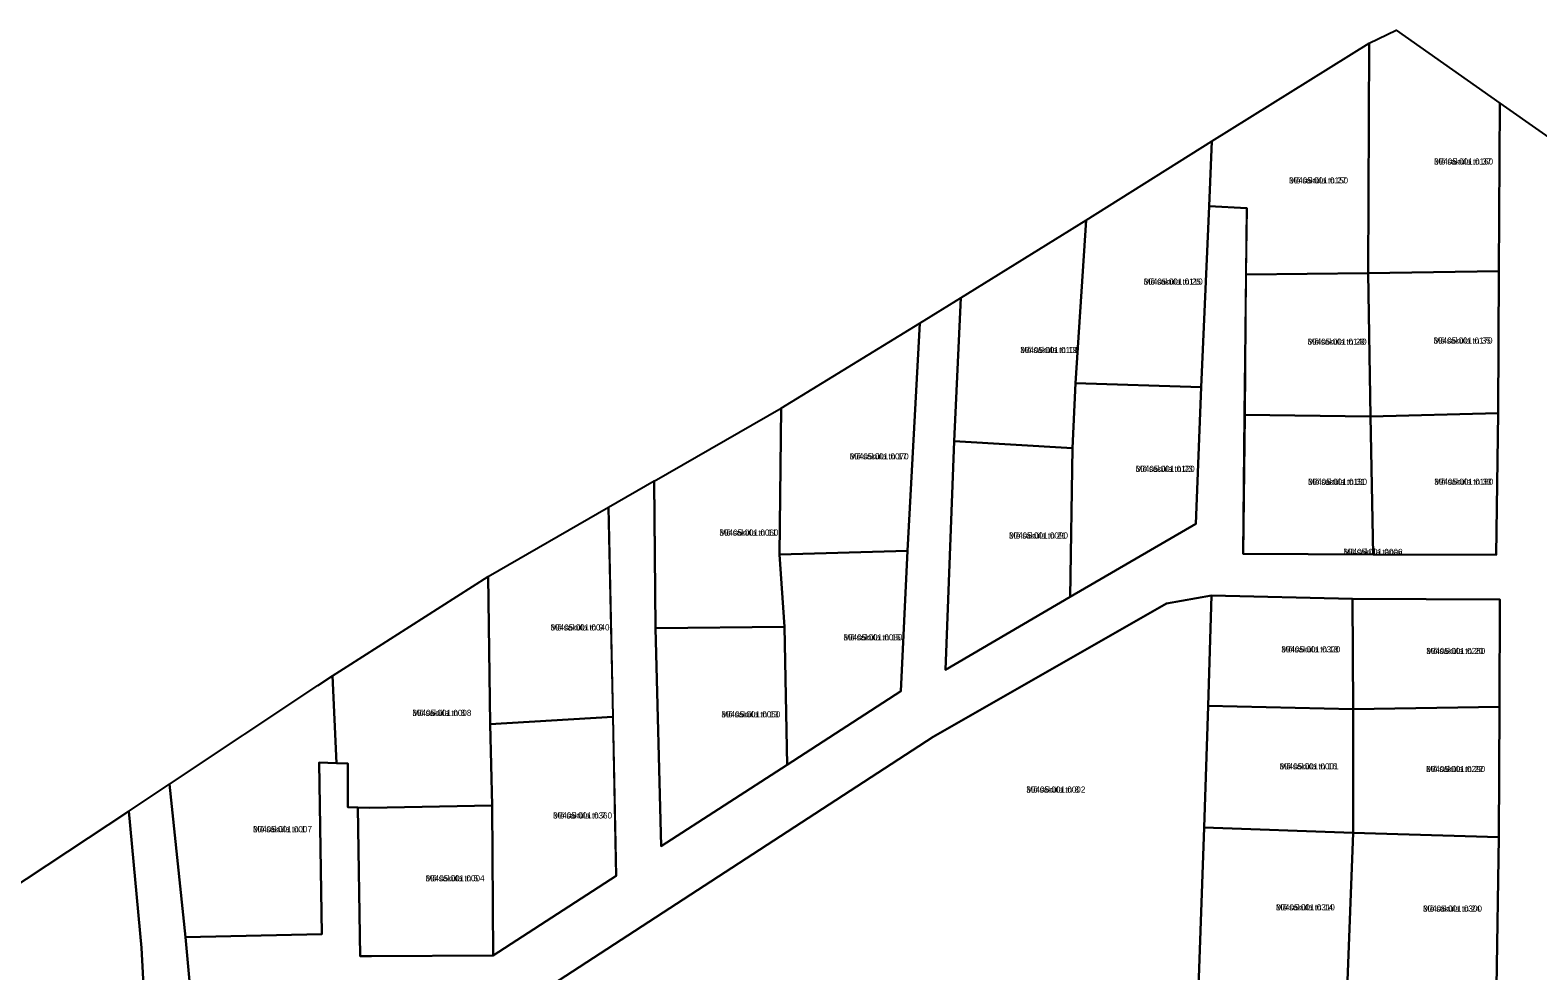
# Model space of a CAD drawing. Extents: x 542681 to 554572, y 6566489 to 6580482.
# Drawn here: x 547346 to 547716.5, y 6577162.8 to 6577394.2 of the extents above; entities that cross this region are included whole.
import ezdxf

# ---------------------------------------------------------------- set-up
doc = ezdxf.new("R2010")
doc.units = 0
for name, color, linetype in [('L_AADRESS', 7, 'Continuous'), ('PIIR', 7, 'Continuous'), ('TUNNUS', 7, 'Continuous')]:
    doc.layers.add(name, color=color, linetype=linetype)

msp = doc.modelspace()

# ---------------------------------------------------------------- linework, layer by layer
at = {"layer": 'PIIR'}
for points in [[(547644.82, 6577334.1), (547644.97, 6577350.38), (547635.72, 6577350.9), (547636.39, 6577366.9), (547675.03, 6577390.99), (547674.84, 6577334.44)], [(547675.03, 6577390.99), (547681.67, 6577394.18), (547707.19, 6577376.23), (547706.93, 6577334.87), (547674.84, 6577334.44)], [(547605.52, 6577347.47), (547636.39, 6577366.9), (547635.72, 6577350.9), (547633.79, 6577306.42), (547602.91, 6577307.35)], [(547574.67, 6577328.33), (547605.52, 6577347.47), (547602.91, 6577307.35), (547602.17, 6577291.41), (547573.06, 6577293.09)], [(547644.82, 6577334.1), (547674.84, 6577334.44), (547675.39, 6577299.16), (547644.46, 6577299.58)], [(547674.84, 6577334.44), (547706.93, 6577334.87), (547706.75, 6577299.95), (547675.39, 6577299.16)], [(547530.53, 6577301.2), (547564.65, 6577322.1), (547561.61, 6577266.15), (547530.1, 6577265.24)], [(547633.79, 6577306.42), (547632.45, 6577272.8), (547601.58, 6577254.82), (547602.17, 6577291.41), (547602.91, 6577307.35)], [(547499.35, 6577283.27), (547530.53, 6577301.2), (547530.1, 6577265.24), (547531.4, 6577247.45), (547499.7, 6577247.1)], [(547644.46, 6577299.58), (547675.39, 6577299.16), (547676.01, 6577265.26), (547644.06, 6577265.43)], [(547675.39, 6577299.16), (547706.75, 6577299.95), (547706.26, 6577265.14), (547676.01, 6577265.26)], [(547573.06, 6577293.09), (547602.17, 6577291.41), (547601.58, 6577254.82), (547570.9, 6577236.84)], [(547489.18, 6577225.35), (547459.02, 6577223.54), (547458.55, 6577259.85), (547488.12, 6577276.89)], [(547559.93, 6577231.66), (547532, 6577213.52), (547531.4, 6577247.45), (547530.1, 6577265.24), (547561.61, 6577266.15)], [(547420.28, 6577235.38), (547423.89, 6577237.69), (547458.55, 6577259.85), (547459.02, 6577223.54), (547459.55, 6577203.48), (547429.34, 6577202.96), (547426.5, 6577203.05), (547424.04, 6577203.11), (547424.05, 6577213.85), (547421.24, 6577213.95)], [(547472.42, 6577158.24), (547567.94, 6577220.42), (547625.27, 6577253.21), (547636.34, 6577255.13), (547635.46, 6577228.02), (547634.51, 6577198.07), (547633.12, 6577158.82), (547605.31, 6577158.73), (547569.42, 6577158.61), (547533.68, 6577158.5), (547497.57, 6577158.43)], [(547636.34, 6577255.13), (547670.95, 6577254.35), (547671.11, 6577227.17), (547635.46, 6577228.02)], [(547670.95, 6577254.35), (547707.18, 6577254.17), (547707.11, 6577227.76), (547671.11, 6577227.17)], [(547532, 6577213.52), (547501.05, 6577193.5), (547499.7, 6577247.1), (547531.4, 6577247.45)], [(547380.22, 6577208.72), (547416.67, 6577232.98), (547420.28, 6577235.38), (547421.24, 6577213.95), (547416.99, 6577214.06), (547417.69, 6577171.85), (547384.17, 6577171.13)], [(547635.46, 6577228.02), (547671.11, 6577227.17), (547671.14, 6577196.78), (547634.51, 6577198.07)], [(547671.11, 6577227.17), (547707.11, 6577227.76), (547706.91, 6577195.71), (547671.14, 6577196.78)], [(547459.55, 6577203.48), (547459.02, 6577223.54), (547489.18, 6577225.35), (547489.96, 6577186.18), (547459.79, 6577166.63)], [(547426.5, 6577203.05), (547429.34, 6577202.96), (547459.55, 6577203.48), (547459.79, 6577166.63), (547429.88, 6577166.46), (547427.11, 6577166.46)], [(547634.51, 6577198.07), (547671.14, 6577196.78), (547669.68, 6577158.28), (547641.57, 6577157.83), (547633.12, 6577158.82)], [(547669.68, 6577158.28), (547671.14, 6577196.78), (547706.91, 6577195.71), (547706.39, 6577158.87), (547677.53, 6577158.35)]]:
    msp.add_lwpolyline(points, close=True, dxfattribs=at)
for points in [[(547385.71, 6577154.03), (547384.17, 6577171.13), (547417.69, 6577171.85), (547416.99, 6577214.06), (547421.24, 6577213.95), (547424.05, 6577213.85), (547424.04, 6577203.11), (547426.5, 6577203.05), (547427.11, 6577166.46), (547429.88, 6577166.46), (547459.79, 6577166.63), (547489.96, 6577186.18), (547489.29, 6577225.38), (547488.12, 6577276.89), (547499.35, 6577283.32), (547499.7, 6577247.1), (547501.05, 6577193.5), (547532, 6577213.52), (547559.93, 6577231.66), (547561.61, 6577266.15), (547564.65, 6577322.1), (547574.67, 6577328.33), (547573.06, 6577293.09), (547570.9, 6577236.84), (547601.58, 6577254.82), (547632.45, 6577272.8), (547633.79, 6577306.42), (547635.72, 6577350.9), (547644.97, 6577350.38), (547644.77, 6577334.22), (547644.49, 6577299.52), (547644.06, 6577265.43), (547676.01, 6577265.26), (547706.26, 6577265.14), (547706.75, 6577299.95), (547706.93, 6577334.87), (547707.19, 6577376.23), (547737.58, 6577354.9)], [(547706.39, 6577158.87), (547706.91, 6577195.71), (547707.11, 6577227.76), (547707.18, 6577254.17), (547670.95, 6577254.35), (547636.34, 6577255.13), (547625.27, 6577253.21), (547567.94, 6577220.42), (547472.42, 6577158.24)], [(547365.05, 6576678.82), (547366.14, 6576847.48), (547372.9, 6576962.73), (547379.3, 6577030.03), (547379.42, 6577054.81), (547373.29, 6577168.48), (547370.25, 6577202.13), (547380.22, 6577208.72), (547384.14, 6577171.11), (547385.71, 6577154.03), (547386.78, 6577116.38), (547387.83, 6577116.57), (547392.31, 6577055.06), (547391.86, 6577051.02), (547390.49, 6577037.28), (547390.15, 6577032.14), (547388.95, 6577019.68), (547387.52, 6576999.24), (547384.13, 6576962.45), (547381.71, 6576921), (547378.68, 6576869.2), (547380.13, 6576867.09), (547380.13, 6576847.05), (547379.04, 6576678.28)], [(547274.87, 6577139.04), (547370.25, 6577202.13), (547373.29, 6577168.48), (547379.42, 6577054.81), (547379.3, 6577030.03), (547372.9, 6576962.73), (547366.14, 6576847.48), (547365.05, 6576678.82), (547361.87, 6576553.76), (547357.84, 6576545.81), (547342.59, 6576529.51)]]:
    msp.add_lwpolyline(points, dxfattribs=at)

# ---------------------------------------------------------------- texts
at = {"layer": 'L_AADRESS'}
for s, p in [('Mõisaküla tn 37', (547691.02, 6577361.13)), ('Mõisaküla tn 27', (547655.38, 6577356.48)), ('Mõisaküla tn 25', (547619.65, 6577331.6)), ('Mõisaküla tn 29', (547659.93, 6577316.82)), ('Mõisaküla tn 35', (547690.89, 6577317.1)), ('Mõisaküla tn 19', (547589.29, 6577314.78)), ('Mõisaküla tn 17', (547547.38, 6577288.63)), ('Mõisaküla tn 23', (547617.68, 6577285.55)), ('Mõisaküla tn 31', (547660.04, 6577282.36)), ('Mõisaküla tn 33', (547691.07, 6577282.38)), ('Mõisaküla tn 11', (547515.38, 6577269.88)), ('Mõisaküla tn 21', (547586.54, 6577269.16)), ('Mõisaküla tänav', (547668.75, 6577265.13)), ('Mõisaküla tn 9', (547473.86, 6577246.55)), ('Mõisaküla tn 15', (547545.86, 6577244.11)), ('Mõisaküla tn 18', (547653.46, 6577241.15)), ('Mõisaküla tn 20', (547689.09, 6577240.76)), ('Mõisaküla tn 3', (547439.91, 6577225.54)), ('Mõisaküla tn 13', (547515.85, 6577225.18)), ('Mõisaküla tn 16', (547653.04, 6577212.4)), ('Mõisaküla tn 22', (547689.07, 6577211.74)), ('Mõisaküla tn 8', (547590.81, 6577206.68)), ('Mõisaküla tn 7', (547474.49, 6577200.31)), ('Mõisaküla tn 1', (547400.73, 6577196.93)), ('Mõisaküla tn 5', (547443.14, 6577184.87)), ('Mõisaküla tn 14', (547652.13, 6577177.72)), ('Mõisaküla tn 24', (547688.29, 6577177.41))]:
    msp.add_text(s, height=1.5, dxfattribs=at).set_placement(p)
at = {"layer": 'TUNNUS'}
for s, p in [('30405:001:0160', (547691.02, 6577361.13)), ('30405:001:0150', (547655.38, 6577356.48)), ('30405:001:0110', (547619.65, 6577331.6)), ('30405:001:0140', (547659.93, 6577316.82)), ('30405:001:0170', (547690.89, 6577317.1)), ('30405:001:0100', (547589.29, 6577314.78)), ('30405:001:0070', (547547.38, 6577288.63)), ('30405:001:0120', (547617.68, 6577285.55)), ('30405:001:0130', (547660.04, 6577282.36)), ('30405:001:0180', (547691.07, 6577282.38)), ('30405:001:0060', (547515.38, 6577269.88)), ('30405:001:0090', (547586.54, 6577269.16)), ('30405:001:0006', (547668.75, 6577265.13)), ('30405:001:0040', (547473.86, 6577246.55)), ('30405:001:0080', (547545.86, 6577244.11)), ('30405:001:0320', (547653.46, 6577241.15)), ('30405:001:0280', (547689.09, 6577240.76)), ('30405:001:0008', (547439.91, 6577225.54)), ('30405:001:0050', (547515.85, 6577225.18)), ('30405:001:0001', (547653.04, 6577212.4)), ('30405:001:0290', (547689.07, 6577211.74)), ('30405:001:0002', (547590.81, 6577206.68)), ('30405:001:0360', (547474.49, 6577200.31)), ('30405:001:0007', (547400.73, 6577196.93)), ('30405:001:0004', (547443.14, 6577184.87)), ('30405:001:0310', (547652.13, 6577177.72)), ('30405:001:0300', (547688.29, 6577177.41))]:
    msp.add_text(s, height=1.5, dxfattribs=at).set_placement(p)

doc.saveas('drawing.dxf')
